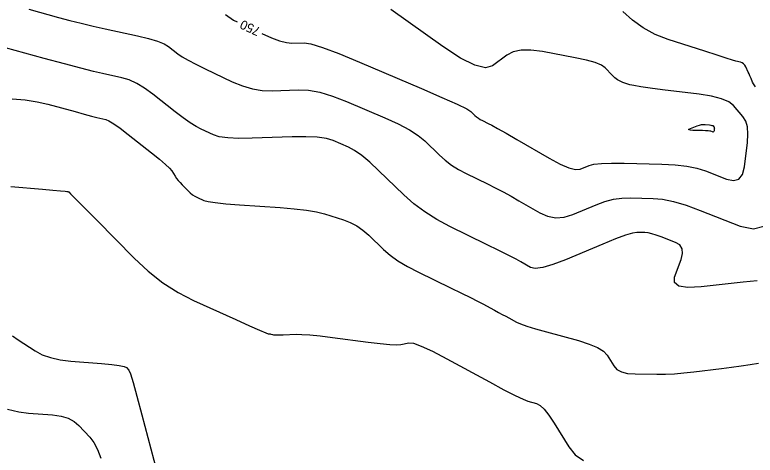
# Model space of a CAD drawing. Extents: x 2082232 to 2083549, y 592624 to 593832.
# Drawn here: x 2082675.1 to 2082731.8, y 592682.3 to 592716.1 of the extents above; entities that cross this region are included whole.
import ezdxf

# ---------------------------------------------------------------- set-up
doc = ezdxf.new("R2010")
doc.units = 0
doc.layers.add('DT_X_Contour_Major', color=7, linetype='Continuous')
doc.layers.add('DT_X_Contour_Minor', color=7, linetype='Continuous')

msp = doc.modelspace()

# ---------------------------------------------------------------- linework, layer by layer
at = {"layer": 'DT_X_Contour_Major'}
for points in [[(2082730.164, 592709.135), (2082729.8, 592709.423), (2082729.24, 592709.664), (2082728.483, 592709.86), (2082727.531, 592710.01), (2082724.729, 592710.35), (2082723.784, 592710.47), (2082723.051, 592710.574), (2082722.529, 592710.664), (2082722.218, 592710.738), (2082721.672, 592710.915), (2082721.468, 592711), (2082721.265, 592711.121), (2082721.064, 592711.277), (2082720.864, 592711.47), (2082720.333, 592712.032), (2082720.041, 592712.238), (2082719.561, 592712.436), (2082718.895, 592712.625), (2082718.042, 592712.806), (2082715.517, 592713.276), (2082714.637, 592713.391), (2082713.89, 592713.384), (2082713.277, 592713.256), (2082712.798, 592713.005), (2082711.699, 592712.175), (2082711.152, 592712.035), (2082710.335, 592712.239), (2082709.248, 592712.786), (2082707.891, 592713.677), (2082703.913, 592716.509)], [(2082691.231, 592716.121), (2082691.858, 592715.684), (2082692.132, 592715.554)], [(2082694.03, 592714.655), (2082694.75, 592714.335), (2082695.384, 592714.101), (2082695.906, 592713.966), (2082696.315, 592713.93), (2082697.254, 592713.963), (2082697.784, 592713.879), (2082698.671, 592713.602), (2082699.914, 592713.131), (2082701.514, 592712.466), (2082706.254, 592710.436), (2082707.824, 592709.756), (2082708.979, 592709.238), (2082709.718, 592708.882), (2082710.042, 592708.687), (2082710.352, 592708.385), (2082710.474, 592708.275), (2082710.61, 592708.174), (2082710.76, 592708.079), (2082710.922, 592707.993), (2082711.373, 592707.772), (2082711.636, 592707.632), (2082712.089, 592707.38), (2082712.731, 592707.013), (2082713.561, 592706.534), (2082716.029, 592705.103), (2082716.871, 592704.648), (2082717.548, 592704.354), (2082718.059, 592704.221), (2082718.404, 592704.251), (2082719.103, 592704.545), (2082719.468, 592704.638), (2082720.037, 592704.697), (2082720.81, 592704.722), (2082721.787, 592704.714), (2082724.666, 592704.644), (2082725.686, 592704.592), (2082726.585, 592704.489), (2082727.364, 592704.333), (2082728.023, 592704.125), (2082729.619, 592703.502), (2082730.154, 592703.385), (2082730.562, 592703.501), (2082730.841, 592703.85), (2082730.994, 592704.431), (2082731.23, 592706.292), (2082731.274, 592706.941), (2082731.23, 592707.494), (2082731.097, 592707.949), (2082730.875, 592708.308), (2082730.164, 592709.135)], [(2082674.907, 592691.46), (2082675.349, 592691.159), (2082676.649, 592690.309), (2082677.186, 592690.021), (2082677.821, 592689.796), (2082678.555, 592689.632), (2082679.387, 592689.53), (2082681.736, 592689.341), (2082682.516, 592689.269), (2082683.094, 592689.195), (2082683.47, 592689.119), (2082683.643, 592689.041), (2082683.837, 592688.83), (2082683.954, 592688.557), (2082684.158, 592687.895), (2082684.451, 592686.844), (2082684.832, 592685.405), (2082685.964, 592681.048)]]:
    msp.add_lwpolyline(points, dxfattribs=at)
at = {"layer": 'DT_X_Contour_Minor'}
for points in [[(2082676.153, 592716.53), (2082678.436, 592715.906), (2082679.301, 592715.676), (2082680.185, 592715.453), (2082681.087, 592715.238), (2082682.008, 592715.03), (2082684.489, 592714.486), (2082685.336, 592714.282), (2082686.016, 592714.076), (2082686.53, 592713.87), (2082686.877, 592713.662), (2082687.581, 592713.108), (2082687.909, 592712.879), (2082688.367, 592712.611), (2082688.953, 592712.301), (2082689.669, 592711.952), (2082691.749, 592710.965), (2082692.525, 592710.645), (2082693.292, 592710.424), (2082694.052, 592710.302), (2082694.803, 592710.279), (2082696.794, 592710.35), (2082697.586, 592710.314), (2082698.468, 592710.153), (2082699.44, 592709.867), (2082700.502, 592709.456), (2082703.454, 592708.192), (2082704.475, 592707.726), (2082705.324, 592707.276), (2082706, 592706.843), (2082706.505, 592706.427), (2082707.622, 592705.337), (2082708.064, 592704.942), (2082708.554, 592704.575), (2082709.092, 592704.235), (2082709.677, 592703.923), (2082711.302, 592703.128), (2082711.909, 592702.824), (2082712.515, 592702.507), (2082713.117, 592702.178), (2082713.717, 592701.837), (2082715.313, 592700.912), (2082715.92, 592700.644), (2082716.545, 592700.532), (2082717.186, 592700.578), (2082717.846, 592700.78), (2082719.627, 592701.529), (2082720.293, 592701.773), (2082720.955, 592701.942), (2082721.615, 592702.038), (2082722.27, 592702.059), (2082724.014, 592702.017), (2082724.73, 592701.947), (2082725.569, 592701.77), (2082726.532, 592701.484), (2082727.618, 592701.09), (2082730.68, 592699.895)], [(2082731.855, 592710.575), (2082731.694, 592710.796), (2082731.614, 592710.936), (2082731.509, 592711.205), (2082731.466, 592711.311), (2082731.415, 592711.43), (2082731.356, 592711.561), (2082731.289, 592711.704), (2082731.101, 592712.101), (2082731.022, 592712.236), (2082730.928, 592712.342), (2082730.818, 592712.418), (2082730.691, 592712.465), (2082730.334, 592712.553), (2082730.085, 592712.625), (2082729.607, 592712.773), (2082728.9, 592712.999), (2082727.964, 592713.302), (2082725.163, 592714.212), (2082724.157, 592714.602), (2082723.241, 592715.091), (2082722.414, 592715.677), (2082721.676, 592716.362)], [(2082731.97, 592695.686), (2082730.898, 592695.577), (2082727.683, 592695.228), (2082726.651, 592695.177), (2082725.968, 592695.284), (2082725.633, 592695.549), (2082725.646, 592695.974), (2082726.145, 592697.317), (2082726.258, 592697.778), (2082726.223, 592698.152), (2082726.04, 592698.44), (2082725.709, 592698.641), (2082724.628, 592699.063), (2082724.245, 592699.202), (2082723.907, 592699.303), (2082723.612, 592699.365), (2082723.362, 592699.39), (2082722.753, 592699.405), (2082722.419, 592699.353), (2082721.874, 592699.187), (2082721.118, 592698.907), (2082720.15, 592698.513), (2082717.287, 592697.309), (2082716.314, 592696.934), (2082715.541, 592696.711), (2082714.969, 592696.64), (2082714.597, 592696.721), (2082713.872, 592697.141), (2082713.504, 592697.343), (2082712.94, 592697.634), (2082712.183, 592698.015), (2082711.231, 592698.484), (2082708.432, 592699.854), (2082707.424, 592700.391), (2082706.498, 592700.976), (2082705.654, 592701.609), (2082704.892, 592702.289), (2082702.969, 592704.166), (2082702.283, 592704.805), (2082701.669, 592705.315), (2082701.126, 592705.695), (2082700.654, 592705.947), (2082699.49, 592706.445), (2082698.965, 592706.604), (2082698.265, 592706.705), (2082697.388, 592706.75), (2082696.334, 592706.737), (2082693.29, 592706.628), (2082692.248, 592706.613), (2082691.403, 592706.65), (2082690.756, 592706.738), (2082690.307, 592706.879), (2082689.373, 592707.321), (2082688.986, 592707.53), (2082688.526, 592707.824), (2082687.992, 592708.204), (2082687.385, 592708.668), (2082685.669, 592710.021), (2082685.036, 592710.48), (2082684.427, 592710.842), (2082683.841, 592711.108), (2082683.279, 592711.277), (2082681.809, 592711.6), (2082681.117, 592711.763), (2082680.142, 592712.01), (2082678.886, 592712.342), (2082677.347, 592712.759), (2082672.868, 592713.982)], [(2082674.873, 592709.652), (2082675.878, 592709.565), (2082676.793, 592709.428), (2082677.619, 592709.24), (2082679.703, 592708.671), (2082680.408, 592708.48), (2082680.96, 592708.332), (2082681.361, 592708.229), (2082681.609, 592708.169), (2082682.069, 592708.068), (2082682.304, 592707.968), (2082682.666, 592707.745), (2082683.153, 592707.397), (2082683.767, 592706.925), (2082685.573, 592705.502), (2082686.178, 592705.016), (2082686.638, 592704.624), (2082686.952, 592704.327), (2082687.122, 592704.123), (2082687.381, 592703.708), (2082687.487, 592703.55), (2082687.611, 592703.388), (2082687.753, 592703.223), (2082687.913, 592703.054), (2082688.363, 592702.597), (2082688.534, 592702.437), (2082688.711, 592702.298), (2082688.892, 592702.18), (2082689.079, 592702.084), (2082689.583, 592701.857), (2082689.895, 592701.772), (2082690.451, 592701.689), (2082691.252, 592701.607), (2082692.298, 592701.527), (2082695.414, 592701.314), (2082696.503, 592701.224), (2082697.436, 592701.111), (2082698.211, 592700.976), (2082698.829, 592700.819), (2082700.268, 592700.372), (2082700.794, 592700.173), (2082701.292, 592699.911), (2082701.762, 592699.586), (2082702.205, 592699.198), (2082703.35, 592698.081), (2082703.84, 592697.659), (2082704.451, 592697.229), (2082705.182, 592696.793), (2082706.034, 592696.349), (2082708.469, 592695.157), (2082709.309, 592694.744), (2082710.003, 592694.399), (2082710.552, 592694.121), (2082710.955, 592693.911), (2082711.836, 592693.441), (2082712.153, 592693.271), (2082712.444, 592693.116), (2082712.707, 592692.974), (2082712.945, 592692.845), (2082713.542, 592692.522), (2082713.852, 592692.384), (2082714.336, 592692.213), (2082714.994, 592692.009), (2082715.826, 592691.773), (2082718.275, 592691.099), (2082719.102, 592690.839), (2082719.746, 592690.566), (2082720.207, 592690.28), (2082720.486, 592689.981), (2082720.985, 592689.165), (2082721.227, 592688.896), (2082721.58, 592688.703), (2082722.043, 592688.584), (2082722.616, 592688.54), (2082724.293, 592688.523), (2082724.942, 592688.53), (2082725.631, 592688.562), (2082726.362, 592688.621), (2082727.133, 592688.705), (2082729.245, 592688.963), (2082730.016, 592689.061), (2082730.746, 592689.159), (2082731.435, 592689.258), (2082732.083, 592689.358)], [(2082727.053, 592707.23), (2082726.836, 592707.245), (2082726.735, 592707.276), (2082726.749, 592707.323), (2082726.878, 592707.386), (2082727.376, 592707.578), (2082727.554, 592707.639), (2082727.716, 592707.678), (2082727.862, 592707.696), (2082727.992, 592707.692), (2082728.317, 592707.653), (2082728.426, 592707.636), (2082728.51, 592707.618), (2082728.569, 592707.596), (2082728.604, 592707.572), (2082728.662, 592707.504), (2082728.68, 592707.475), (2082728.691, 592707.437), (2082728.695, 592707.392), (2082728.691, 592707.339), (2082728.672, 592707.186), (2082728.659, 592707.138), (2082728.636, 592707.109), (2082728.603, 592707.1), (2082728.559, 592707.11), (2082728.428, 592707.161), (2082728.351, 592707.178), (2082728.217, 592707.193), (2082728.028, 592707.204), (2082727.782, 592707.212), (2082727.053, 592707.23)], [(2082674.793, 592702.921), (2082677.212, 592702.712), (2082678.009, 592702.643), (2082678.585, 592702.593), (2082678.94, 592702.562), (2082679.073, 592702.549), (2082679.135, 592702.539), (2082679.156, 592702.535), (2082679.173, 592702.531), (2082679.187, 592702.527), (2082679.198, 592702.523), (2082679.22, 592702.511), (2082679.361, 592702.371), (2082679.767, 592701.961), (2082680.439, 592701.281), (2082681.376, 592700.331), (2082684.229, 592697.438), (2082685.316, 592696.42), (2082686.438, 592695.538), (2082687.596, 592694.79), (2082688.789, 592694.177), (2082692.016, 592692.723), (2082693.08, 592692.246), (2082693.848, 592691.904), (2082694.323, 592691.698), (2082694.502, 592691.628), (2082694.589, 592691.622), (2082694.623, 592691.618), (2082694.658, 592691.612), (2082694.695, 592691.604), (2082694.735, 592691.592), (2082694.842, 592691.559), (2082694.923, 592691.55), (2082695.086, 592691.546), (2082695.331, 592691.549), (2082695.657, 592691.557), (2082696.637, 592691.588), (2082697.087, 592691.582), (2082697.701, 592691.539), (2082698.48, 592691.46), (2082699.424, 592691.344), (2082702.161, 592690.987), (2082703.088, 592690.876), (2082703.815, 592690.81), (2082704.342, 592690.79), (2082704.669, 592690.815), (2082705.277, 592690.941), (2082705.629, 592690.899), (2082706.232, 592690.679), (2082707.084, 592690.281), (2082708.187, 592689.704), (2082711.46, 592687.929), (2082712.565, 592687.337), (2082713.426, 592686.895), (2082714.042, 592686.603), (2082714.414, 592686.459), (2082715.079, 592686.276), (2082715.35, 592686.13), (2082715.663, 592685.831), (2082716.018, 592685.377), (2082716.416, 592684.77), (2082717.532, 592682.945), (2082718.027, 592682.345), (2082718.676, 592681.913)], [(2082730.68, 592699.895), (2082731.705, 592699.671), (2082732.487, 592699.893)], [(2082674.526, 592685.848), (2082675.399, 592685.647), (2082676.149, 592685.542), (2082677.988, 592685.394), (2082678.63, 592685.303), (2082679.179, 592685.14), (2082679.635, 592684.904), (2082679.998, 592684.597), (2082680.84, 592683.682), (2082681.144, 592683.276), (2082681.423, 592682.746), (2082681.679, 592682.091)]]:
    msp.add_lwpolyline(points, dxfattribs=at)

# ---------------------------------------------------------------- texts
at = {"layer": 'DT_X_Contour_Major'}
msp.add_text('750', height=0.7, rotation=154.6463, dxfattribs=at).set_placement((2082693.972, 592715.069))

doc.saveas('drawing.dxf')
